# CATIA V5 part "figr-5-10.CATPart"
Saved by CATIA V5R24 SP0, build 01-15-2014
Part number: Part1
Bounding box of the stored display mesh (mm): x 0 to 150, y -70 to 70, z -150 to 69.804
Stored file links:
  D:\KAVITA\CATIA V5-6R2014 Project_ Kavita\CATIA V5-6R2014_partfiles\Partfiles\c05_catia_v5-6r2014_prt\figr-5-10.CATPart
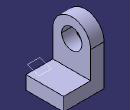
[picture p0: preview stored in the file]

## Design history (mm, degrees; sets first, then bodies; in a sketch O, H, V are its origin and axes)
Set1
  Plane1: type 2Lines, Element1 edge of Pad2, Element2 edge of Pad2
Body1 (main body)
  Sketch1 on yz-plane, origin (0, 0, 0), H (0, 1, 0), V (0, 0, 1)
    arc A1 centre (0, 0) radius 70 from (70, 0) to (-70, 0) ccw
    point P1 (70, 0)
    point P2 (-70, 0)
    line L1 (-70, 0) -> (-70, -150)
    line L2 (-70, -150) -> (70, -150)
    line L3 (70, -150) -> (70, 0)
    circle A2 centre (0, 0) radius 37.5
    radius A1 = 70
    radius A2 = 37.5
    distance O L2 = 150
    coincidence: P1 H, P2 H
    tangency: L1 A1, L3 A1
    horizontal: L2 H
  Pad1: profile Sketch1, direction (1, 0, 0), length 50
  Sketch2 on face of Pad1, origin (50, 0, 0), H (0, 1, 0), V (0, 0, 1)
    line L1 (-70, -150) -> (70, -150)
    line L2 (70, -150) -> (70, -100)
    line L3 (70, -100) -> (-70, -100)
    line L4 (-70, -100) -> (-70, -150)
    reference projected line E1 (-70, -150) -> (70, -150) from edge [face of Pad1 | face of Pad1]
    reference projected line E2 (-70, 0) -> (-70, -150) from edge [face of Pad1 | face of Pad1]
    reference projected line E3 (70, -150) -> (70, 0) from edge [face of Pad1 | face of Pad1]
    length L2 = 50
    horizontal: L1 H, L3 H
    vertical: L2 V, L4 V
    coincidence: L1 E1, E2 L4, L2 E3
  Pad2: profile Sketch2, direction (1, 0, 0), length 100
